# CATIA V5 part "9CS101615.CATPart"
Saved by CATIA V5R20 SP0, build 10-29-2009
Part number: 9CS101615
Revision: ANY
Definition: UNKNOWN
Nomenclature: 9CS101615
Source: Unknown
Bounding box of the stored display mesh (mm): x -8 to 8, y -7.5 to 7.5, z -8 to 8
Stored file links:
  C:\Users\Utente\Desktop\IO LAVORO\3D X SITO CF\CUMSA\3D files PW\pw101430\pw101430_ejection\9CS101615.CATPart
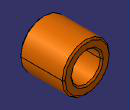
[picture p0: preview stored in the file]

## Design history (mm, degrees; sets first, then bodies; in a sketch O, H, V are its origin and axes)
Body1 "Revolución1" (main body)
  Solid1: solid without history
